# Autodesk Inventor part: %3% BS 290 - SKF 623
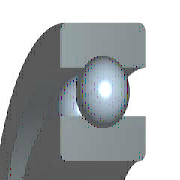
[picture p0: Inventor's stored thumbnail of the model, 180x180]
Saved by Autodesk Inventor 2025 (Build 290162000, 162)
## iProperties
Created: 2024-01
Part Number: %3% BS 290 - SKF 623
Material: Acciaio, Dolce
Description: Cuscinetti a sfere a fila singola
Document SubType Name: Modeling
Standard: BS 290
Designer: Ryzen5700u
Standards Organization: BSI
Language: it-IT
Size Designation: SKF 623
Categories: <MemberInstance><Categories><Category DisplayName="Parti albero" InternalName="7f7aeb1f-a693-4053-b835-cee3144e0d98" Mnemonic="SHFT"><Category DisplayName="Cusc
Density: 7.85 g/cm^3
Appearance: Semilucidato
IsCustomPart: 0
Author: Ryzen5700u
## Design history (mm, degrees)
node "WorkPoint1"
node "WorkAxis1"
node "WorkPlane3"
node "WorkPlane4"
node "WorkPoint2"
pattern_circular "Seriepolare1" dims "d17" = 50.42857 (= msp_pocet), angle "d19" = 360 deg
body "Solid1"
node "Schizzo1"
revolve "Rivoluzione1" stored, may be unused: angle "d6" = 360 deg
revolve "Rivoluzione2" stored, may be unused: angle "d10" = 360 deg
node "Schizzo4"
revolve "Rivoluzione3" stored, may be unused: angle "d16" = 360 deg
fillet "Raccordo1" dims "d20" = 0.15 (= r)
sketch "Schizzo2"
  geometry: L1 (1.5, 4)-(5, 4); L2 (1.5, 0)-(1.5, 4); L3 (5, 0)-(1.5, 0); L4 (5, 4)-(5, 0); L5 (0, 0)-(0, 20); L6 (0, 0)-(0, 20); L7 (-7.2, 0)-(43.2, 0) reference
  constraints: 12 end point, 3 vertical, 2 horizontal, 1 collinear, 1 other
  dimensions: "d1" = 3 diameter of L1.start L5 (= Diam); "d3" = 10 diameter of L1.end L5 (= DD); "d5" = 4 distance of L2.start L1.start (= msp_mdtd2)
sketch "Schizzo3"
  geometry: L1 (3.88, 4)-(3.88, 2.84); L2 (2.62, 4)-(3.88, 4); L3 (2.62, 2.84)-(2.62, 4); L4 (2.62, 0)-(2.62, 1.16); L5 (3.88, 0)-(2.62, 0); L6 (3.88, 1.16)-(3.88, 0); L7 (5, 0)-(-5, 0) reference; L8 (5, 4)-(-5, 4) reference; L9 (0, -42.29)-(0, 61.29); L10 (0, 82.007)-(0, -63.007) reference; A1 r 1.05 centre (3.25, 2) between (3.88, 1.16) and (3.88, 2.84); A2 r 1.05 centre (3.25, 2) between (2.62, 2.84) and (2.62, 1.16)
  constraints: 14 end point, 4 collinear, 4 point on circle, 4 vertical, 2 centre point, 2 concentric, 2 horizontal, 2 point on line
  dimensions: "d9" = 2.1 diameter of A1 (= msp_mdtd6); "d21" = 2.62 distance between parallel lines of L9 L4 (= 0.5 x msp_d1); "d22" = 3.25 distance from line of L9 A1.centre (= 0.5 x msp_ds); "d23" = 3.88 distance between parallel lines of L9 L6 (= 0.5 x msp_dd1)
sketch "Schizzo5"
  geometry: L1 (3.25, 0.95)-(3.25, 3.05); L2 (3.88, 0)-(-3.88, 0) reference; L3 (3.25, 0.95)-(3.25, 3.05); A1 r 1.05 centre (3.25, 2) between (3.25, 0.95) and (3.25, 3.05); A2 r 1.05 centre (3.25, 2) between (3.88, 1.16) and (3.88, 2.84) reference
  constraints: 4 end point, 2 point on circle, 1 centre point, 1 concentric, 1 vertical
  dimensions: "d13" = 0 horizontal distance of A1.centre L1.start; "d15" = 2.1001 diameter of A1 (computed from msp_mdtd6)
other parameters: "Diam" = 3 [user parameter; used in 3 equation terms], "DD" = 10 [user parameter; used in 3 equation terms], "B" = 4 [user parameter; used in 1 equation term], "r" = 0.15 [user parameter; used in 1 equation term], "msp_ds" = 6.5 (= 0.5 x Diam + 0.5 x DD) [user parameter; used in 5 equation terms], "msp_d0" = 2.1 (= -0.3 x Diam + 0.3 x DD) [user parameter; used in 4 equation terms], "msp_d1" = 5.24 (= msp_ds - 0.6 x msp_d0) [user parameter; used in 1 equation term], "msp_dd1" = 7.76 (= msp_ds + 0.6 x msp_d0) [user parameter; used in 1 equation term], "msp_pom" = 9.75 (= 1.5 x msp_ds) [user parameter; used in 1 equation term], "msp_mdtd2" = 4 (= B) [user parameter; used in 3 equation terms], "msp_mdtd4" = 6.5 (= msp_ds) [user parameter], "msp_mdtd6" = 2.1 (= msp_d0) [user parameter; used in 2 equation terms], "msp_mdtd7" = 2 (= 0.5 x msp_mdtd2) [user parameter], "msp_pocet" = 50.42857 (computed from msp_d0, msp_pom) [user parameter; used in 1 equation term], "d2" = 72 (derived), "d4" = 19 (derived), "d7" = 0, "d8" = 15.6 (derived), "d11" = -4 (computed from msp_mdtd2), "d12" = 0 (derived), "d14" = 15.6001 (derived), "d26" = 0, "d27" = 0, "d28" = 0, "d29" = 0, "d30" = 0
